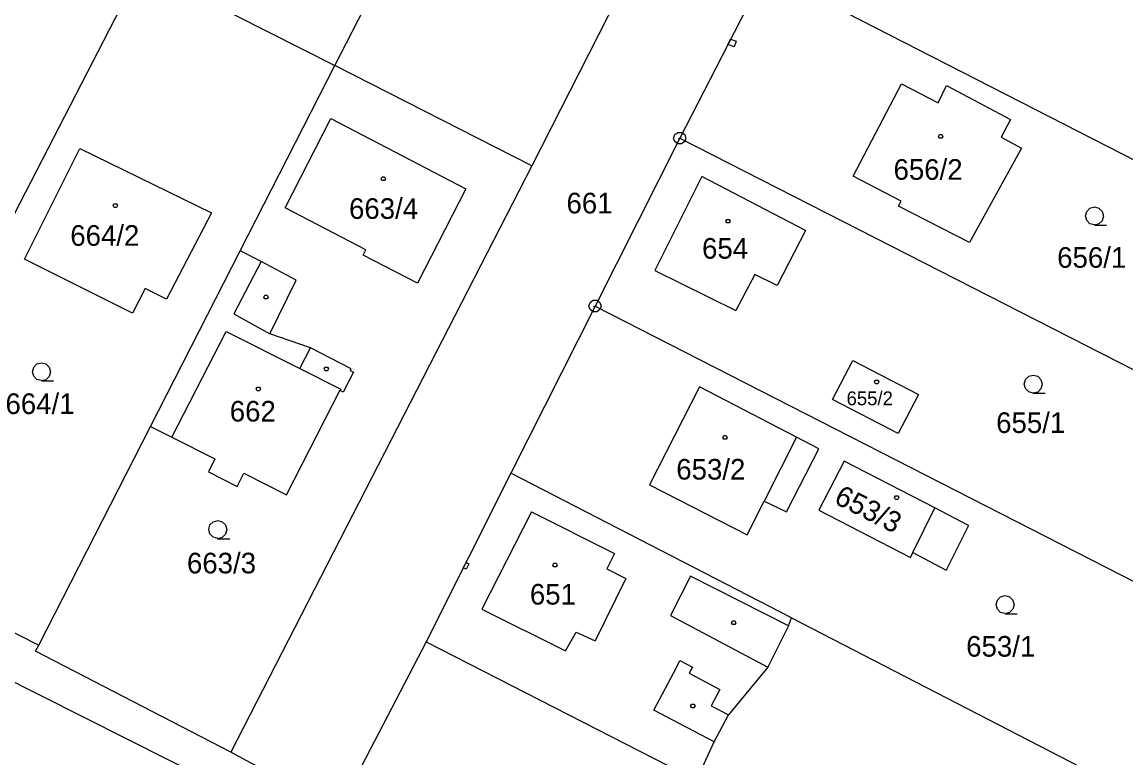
# Model space of a CAD drawing. Extents: x -759699 to -757730, y -1172308 to -1170857.
# Drawn here: x -758455.8 to -758364.9, y -1171339 to -1171278.3 of the extents above; entities that cross this region are included whole.
import ezdxf

# ---------------------------------------------------------------- set-up
doc = ezdxf.new("R2010")
doc.units = 0
for name, color, linetype in [('Vrstva 1', 7, 'Continuous'), ('Vrstva 12', 7, 'Continuous'), ('Vrstva 13', 7, 'Continuous'), ('Vrstva 2', 7, 'Continuous'), ('Vrstva 3', 7, 'Continuous'), ('Vrstva 4', 7, 'Continuous'), ('Vrstva 5', 7, 'Continuous'), ('Vrstva 8', 7, 'Continuous')]:
    doc.layers.add(name, color=color, linetype=linetype)

msp = doc.modelspace()

# ---------------------------------------------------------------- linework, layer by layer
at = {"layer": 'Vrstva 1'}
for p, q in [((-758389.3, -1171241.95), (-758413.82, -1171290.17)), ((-758430.03, -1171281.91), (-758413.88, -1171250.29)), ((-758446, -1171273.82), (-758470.53, -1171321.45)), ((-758446, -1171273.82), (-758430.03, -1171281.91)), ((-758394.57, -1171274.13), (-758401.62, -1171287.89)), ((-758394.57, -1171274.13), (-758332.15, -1171306.13)), ((-758437.83, -1171297.17), (-758430.03, -1171281.91)), ((-758413.82, -1171290.17), (-758430.03, -1171281.91)), ((-758387.33, -1171291.01), (-758383.36, -1171283.42)), ((-758383.36, -1171283.42), (-758380.34, -1171284.98)), ((-758380.34, -1171284.98), (-758379.66, -1171283.54)), ((-758379.66, -1171283.54), (-758374.38, -1171286.36)), ((-758434.14, -1171293.64), (-758430.37, -1171286.28)), ((-758430.37, -1171286.28), (-758419.24, -1171292.06)), ((-758374.38, -1171286.36), (-758375.16, -1171287.82)), ((-758401.62, -1171287.89), (-758408.6, -1171301.73)), ((-758401.62, -1171287.89), (-758339.63, -1171319.54)), ((-758375.16, -1171287.82), (-758373.46, -1171288.72)), ((-758455.6, -1171297.87), (-758451.06, -1171288.75)), ((-758451.06, -1171288.75), (-758440.2, -1171294.05)), ((-758373.46, -1171288.72), (-758377.77, -1171296.48)), ((-758413.82, -1171290.17), (-758438.62, -1171338.48)), ((-758399.8, -1171291.06), (-758403.67, -1171298.79)), ((-758391.26, -1171295.5), (-758399.8, -1171291.06)), ((-758383.39, -1171293.08), (-758387.33, -1171291.01)), ((-758419.24, -1171292.06), (-758423.24, -1171299.85)), ((-758383.61, -1171293.48), (-758383.39, -1171293.08)), ((-758440.2, -1171294.05), (-758443.9, -1171301.16)), ((-758427.48, -1171297.08), (-758434.14, -1171293.64)), ((-758377.77, -1171296.48), (-758383.61, -1171293.48)), ((-758391.26, -1171295.5), (-758393.61, -1171300.02)), ((-758446.7, -1171302.3), (-758455.6, -1171297.87)), ((-758445.23, -1171311.65), (-758437.83, -1171297.17)), ((-758436.12, -1171298.05), (-758437.83, -1171297.17)), ((-758427.71, -1171297.54), (-758427.48, -1171297.08)), ((-758423.24, -1171299.85), (-758427.71, -1171297.54)), ((-758433.23, -1171299.6), (-758436.12, -1171298.05)), ((-758403.67, -1171298.79), (-758397, -1171302.08)), ((-758435.4, -1171304.02), (-758433.23, -1171299.6)), ((-758395.43, -1171299.13), (-758397, -1171302.08)), ((-758393.61, -1171300.02), (-758395.43, -1171299.13)), ((-758445.66, -1171300.27), (-758446.7, -1171302.3)), ((-758443.9, -1171301.16), (-758445.66, -1171300.27)), ((-758408.6, -1171301.73), (-758415.54, -1171315.5)), ((-758408.6, -1171301.73), (-758347.06, -1171333.18)), ((-758432.06, -1171305.17), (-758435.4, -1171304.02)), ((-758428.71, -1171306.9), (-758432.06, -1171305.17)), ((-758428.78, -1171307.03), (-758428.71, -1171306.9)), ((-758389.05, -1171309.42), (-758387.36, -1171306.2)), ((-758387.36, -1171306.2), (-758381.97, -1171309)), ((-758428.51, -1171307.17), (-758429.35, -1171308.81)), ((-758428.78, -1171307.03), (-758428.51, -1171307.17)), ((-758434.02, -1171317.27), (-758429.62, -1171308.68)), ((-758429.35, -1171308.81), (-758429.62, -1171308.68)), ((-758399.99, -1171308.38), (-758404.12, -1171316.44)), ((-758392.01, -1171312.52), (-758399.99, -1171308.38)), ((-758383.63, -1171312.23), (-758389.05, -1171309.42)), ((-758381.97, -1171309), (-758383.63, -1171312.23)), ((-758454.44, -1171329.67), (-758445.23, -1171311.65)), ((-758445.23, -1171311.65), (-758443.47, -1171312.53)), ((-758443.47, -1171312.53), (-758439.92, -1171314.31)), ((-758390.17, -1171313.48), (-758392.01, -1171312.52)), ((-758392.84, -1171318.69), (-758390.17, -1171313.48)), ((-758439.92, -1171314.31), (-758440.46, -1171315.39)), ((-758388.09, -1171314.5), (-758390.17, -1171318.55)), ((-758380.62, -1171318.36), (-758388.09, -1171314.5)), ((-758440.46, -1171315.39), (-758438.09, -1171316.58)), ((-758438.09, -1171316.58), (-758437.55, -1171315.5)), ((-758437.55, -1171315.5), (-758434.02, -1171317.27)), ((-758415.54, -1171315.5), (-758422.51, -1171329.39)), ((-758392.43, -1171327.41), (-758415.54, -1171315.5)), ((-758439.91, -1171341.05), (-758488.47, -1171316.61)), ((-758404.12, -1171316.44), (-758396.08, -1171320.56)), ((-758396.08, -1171320.56), (-758394.68, -1171317.8)), ((-758394.68, -1171317.8), (-758392.84, -1171318.69)), ((-758390.17, -1171318.55), (-758382.62, -1171322.43)), ((-758377.84, -1171319.8), (-758380.62, -1171318.36)), ((-758377.84, -1171319.8), (-758379.69, -1171323.49)), ((-758470.53, -1171321.45), (-758454.44, -1171329.67)), ((-758382.62, -1171322.43), (-758382.42, -1171322.03)), ((-758382.42, -1171322.03), (-758379.69, -1171323.49)), ((-758392.67, -1171328.08), (-758392.43, -1171327.41)), ((-758392.43, -1171327.41), (-758354.46, -1171346.98)), ((-758392.67, -1171328.08), (-758394.36, -1171331.48)), ((-758454.69, -1171330.17), (-758454.44, -1171329.67)), ((-758422.51, -1171329.39), (-758429.75, -1171343.26)), ((-758422.51, -1171329.39), (-758400.25, -1171340.79)), ((-758438.62, -1171338.48), (-758454.69, -1171330.17)), ((-758394.36, -1171331.48), (-758397.61, -1171335.4)), ((-758398.79, -1171337.64), (-758397.61, -1171335.4)), ((-758400.25, -1171340.79), (-758398.79, -1171337.64)), ((-758429.75, -1171343.26), (-758438.62, -1171338.48))]:
    msp.add_line(p, q, dxfattribs=at)
at = {"layer": 'Vrstva 12'}
for p, q in [((-758387.33, -1171291.01), (-758383.36, -1171283.42)), ((-758383.36, -1171283.42), (-758380.34, -1171284.98)), ((-758380.34, -1171284.98), (-758379.66, -1171283.54)), ((-758379.66, -1171283.54), (-758374.38, -1171286.36)), ((-758434.14, -1171293.64), (-758430.37, -1171286.28)), ((-758430.37, -1171286.28), (-758419.24, -1171292.06)), ((-758374.38, -1171286.36), (-758375.16, -1171287.82)), ((-758375.16, -1171287.82), (-758373.46, -1171288.72)), ((-758455.6, -1171297.87), (-758451.06, -1171288.75)), ((-758451.06, -1171288.75), (-758440.2, -1171294.05)), ((-758373.46, -1171288.72), (-758377.77, -1171296.48)), ((-758399.8, -1171291.06), (-758403.67, -1171298.79)), ((-758391.26, -1171295.5), (-758399.8, -1171291.06)), ((-758383.39, -1171293.08), (-758387.33, -1171291.01)), ((-758419.24, -1171292.06), (-758423.24, -1171299.85)), ((-758383.61, -1171293.48), (-758383.39, -1171293.08)), ((-758440.2, -1171294.05), (-758443.9, -1171301.16)), ((-758427.48, -1171297.08), (-758434.14, -1171293.64)), ((-758377.77, -1171296.48), (-758383.61, -1171293.48)), ((-758391.26, -1171295.5), (-758393.61, -1171300.02)), ((-758446.7, -1171302.3), (-758455.6, -1171297.87)), ((-758427.71, -1171297.54), (-758427.48, -1171297.08)), ((-758423.24, -1171299.85), (-758427.71, -1171297.54)), ((-758403.67, -1171298.79), (-758397, -1171302.08)), ((-758395.43, -1171299.13), (-758397, -1171302.08)), ((-758393.61, -1171300.02), (-758395.43, -1171299.13)), ((-758445.66, -1171300.27), (-758446.7, -1171302.3)), ((-758443.9, -1171301.16), (-758445.66, -1171300.27)), ((-758443.47, -1171312.53), (-758439, -1171303.83)), ((-758439, -1171303.83), (-758432.93, -1171306.87)), ((-758432.93, -1171306.87), (-758429.56, -1171308.56)), ((-758389.05, -1171309.42), (-758387.36, -1171306.2)), ((-758387.36, -1171306.2), (-758381.97, -1171309)), ((-758434.02, -1171317.27), (-758429.62, -1171308.68)), ((-758429.56, -1171308.56), (-758429.62, -1171308.68)), ((-758399.99, -1171308.38), (-758404.12, -1171316.44)), ((-758392.01, -1171312.52), (-758399.99, -1171308.38)), ((-758383.63, -1171312.23), (-758389.05, -1171309.42)), ((-758381.97, -1171309), (-758383.63, -1171312.23)), ((-758443.47, -1171312.53), (-758439.92, -1171314.31)), ((-758392.01, -1171312.52), (-758394.68, -1171317.8)), ((-758439.92, -1171314.31), (-758440.46, -1171315.39)), ((-758388.09, -1171314.5), (-758390.17, -1171318.55)), ((-758380.62, -1171318.36), (-758388.09, -1171314.5)), ((-758440.46, -1171315.39), (-758438.09, -1171316.58)), ((-758438.09, -1171316.58), (-758437.55, -1171315.5)), ((-758437.55, -1171315.5), (-758434.02, -1171317.27)), ((-758404.12, -1171316.44), (-758396.08, -1171320.56)), ((-758396.08, -1171320.56), (-758394.68, -1171317.8)), ((-758413.83, -1171318.67), (-758417.94, -1171326.69)), ((-758413.83, -1171318.67), (-758407, -1171322.1)), ((-758390.17, -1171318.55), (-758382.62, -1171322.43)), ((-758382.42, -1171322.03), (-758380.62, -1171318.36)), ((-758407, -1171322.1), (-758407.64, -1171323.37)), ((-758382.62, -1171322.43), (-758382.42, -1171322.03)), ((-758407.64, -1171323.37), (-758406.08, -1171324.16)), ((-758406.08, -1171324.16), (-758408.6, -1171329.31)), ((-758417.94, -1171326.69), (-758411.03, -1171330.14)), ((-758411.03, -1171330.14), (-758410.16, -1171328.58)), ((-758410.16, -1171328.58), (-758408.6, -1171329.31))]:
    msp.add_line(p, q, dxfattribs=at)
at = {"layer": 'Vrstva 13'}
for p, q in [((-758397.67, -1171280.18), (-758397.44, -1171279.73)), ((-758397.44, -1171279.73), (-758396.97, -1171279.89)), ((-758397.14, -1171280.36), (-758397.67, -1171280.18)), ((-758396.97, -1171279.89), (-758397.14, -1171280.36)), ((-758419.46, -1171323.3), (-758419.23, -1171322.86)), ((-758419.21, -1171323.41), (-758419.46, -1171323.3)), ((-758419.23, -1171322.86), (-758419.01, -1171322.95)), ((-758419.01, -1171322.95), (-758419.21, -1171323.41))]:
    msp.add_line(p, q, dxfattribs=at)
at = {"layer": 'Vrstva 3'}
for points in [[(-758367.45, -1171295.04), (-758367.83, -1171294.94), (-758368.1, -1171294.67), (-758368.2, -1171294.3), (-758368.1, -1171293.93), (-758367.83, -1171293.66), (-758367.46, -1171293.56), (-758367.09, -1171293.66), (-758366.82, -1171293.93), (-758366.72, -1171294.31), (-758366.82, -1171294.69), (-758367.09, -1171294.96), (-758367.47, -1171295.06), (-758366.47, -1171295.06)], [(-758454.2, -1171307.87), (-758454.58, -1171307.77), (-758454.85, -1171307.5), (-758454.95, -1171307.13), (-758454.85, -1171306.76), (-758454.58, -1171306.49), (-758454.21, -1171306.39), (-758453.84, -1171306.49), (-758453.57, -1171306.76), (-758453.47, -1171307.14), (-758453.57, -1171307.52), (-758453.84, -1171307.79), (-758454.22, -1171307.89), (-758453.22, -1171307.89)], [(-758372.5, -1171308.89), (-758372.88, -1171308.79), (-758373.15, -1171308.52), (-758373.25, -1171308.15), (-758373.15, -1171307.78), (-758372.88, -1171307.51), (-758372.51, -1171307.41), (-758372.14, -1171307.51), (-758371.87, -1171307.78), (-758371.77, -1171308.16), (-758371.87, -1171308.54), (-758372.14, -1171308.81), (-758372.52, -1171308.91), (-758371.52, -1171308.91)], [(-758439.68, -1171320.87), (-758440.06, -1171320.77), (-758440.33, -1171320.5), (-758440.43, -1171320.13), (-758440.33, -1171319.76), (-758440.06, -1171319.49), (-758439.69, -1171319.39), (-758439.32, -1171319.49), (-758439.05, -1171319.76), (-758438.95, -1171320.14), (-758439.05, -1171320.52), (-758439.32, -1171320.79), (-758439.7, -1171320.89), (-758438.7, -1171320.89)], [(-758374.81, -1171327.06), (-758375.19, -1171326.96), (-758375.46, -1171326.69), (-758375.56, -1171326.32), (-758375.46, -1171325.95), (-758375.19, -1171325.68), (-758374.82, -1171325.58), (-758374.45, -1171325.68), (-758374.18, -1171325.95), (-758374.08, -1171326.33), (-758374.18, -1171326.71), (-758374.45, -1171326.98), (-758374.83, -1171327.08), (-758373.83, -1171327.08)]]:
    msp.add_lwpolyline(points, dxfattribs=at)
at = {"layer": 'Vrstva 4'}
for p, q in [((-758436.12, -1171298.05), (-758438.36, -1171302.37)), ((-758438.36, -1171302.37), (-758435.4, -1171304.02)), ((-758443.47, -1171312.53), (-758439, -1171303.83)), ((-758439, -1171303.83), (-758432.93, -1171306.87)), ((-758432.93, -1171306.87), (-758432.06, -1171305.17)), ((-758432.93, -1171306.87), (-758429.56, -1171308.56)), ((-758429.56, -1171308.56), (-758429.62, -1171308.68)), ((-758392.01, -1171312.52), (-758394.68, -1171317.8)), ((-758413.83, -1171318.67), (-758417.94, -1171326.69)), ((-758413.83, -1171318.67), (-758407, -1171322.1)), ((-758382.42, -1171322.03), (-758380.62, -1171318.36)), ((-758407, -1171322.1), (-758407.64, -1171323.37)), ((-758407.64, -1171323.37), (-758406.08, -1171324.16)), ((-758406.08, -1171324.16), (-758408.6, -1171329.31)), ((-758400.73, -1171323.99), (-758402.39, -1171327.21)), ((-758392.67, -1171328.08), (-758400.73, -1171323.99)), ((-758417.94, -1171326.69), (-758411.03, -1171330.14)), ((-758402.39, -1171327.21), (-758394.36, -1171331.48)), ((-758411.03, -1171330.14), (-758410.16, -1171328.58)), ((-758410.16, -1171328.58), (-758408.6, -1171329.31)), ((-758403.76, -1171335.02), (-758401.87, -1171331.44)), ((-758401.87, -1171331.44), (-758401.61, -1171330.94)), ((-758401.61, -1171330.94), (-758400.58, -1171331.49)), ((-758400.58, -1171331.49), (-758400.85, -1171331.98)), ((-758400.85, -1171331.98), (-758398.32, -1171333.33)), ((-758398.32, -1171333.33), (-758399.03, -1171334.66)), ((-758398.79, -1171337.64), (-758403.76, -1171335.02)), ((-758399.03, -1171334.66), (-758397.61, -1171335.4))]:
    msp.add_line(p, q, dxfattribs=at)
at = {"layer": 'Vrstva 5'}
for points in [[(-758380.04, -1171287.6), (-758379.95, -1171287.75), (-758380.04, -1171287.9), (-758380.22, -1171287.9), (-758380.31, -1171287.75), (-758380.22, -1171287.6)], [(-758425.96, -1171291.09), (-758425.87, -1171291.24), (-758425.96, -1171291.39), (-758426.14, -1171291.39), (-758426.23, -1171291.24), (-758426.14, -1171291.09)], [(-758448.03, -1171293.3), (-758447.94, -1171293.45), (-758448.03, -1171293.6), (-758448.21, -1171293.6), (-758448.3, -1171293.45), (-758448.21, -1171293.3)], [(-758397.56, -1171294.58), (-758397.47, -1171294.73), (-758397.56, -1171294.88), (-758397.74, -1171294.88), (-758397.83, -1171294.73), (-758397.74, -1171294.58)], [(-758435.62, -1171300.83), (-758435.53, -1171300.98), (-758435.62, -1171301.13), (-758435.8, -1171301.13), (-758435.89, -1171300.98), (-758435.8, -1171300.83)], [(-758430.66, -1171306.75), (-758430.57, -1171306.9), (-758430.66, -1171307.05), (-758430.84, -1171307.05), (-758430.93, -1171306.9), (-758430.84, -1171306.75)], [(-758385.31, -1171307.83), (-758385.22, -1171307.98), (-758385.31, -1171308.13), (-758385.49, -1171308.13), (-758385.58, -1171307.98), (-758385.49, -1171307.83)], [(-758436.26, -1171308.4), (-758436.17, -1171308.55), (-758436.26, -1171308.7), (-758436.44, -1171308.7), (-758436.53, -1171308.55), (-758436.44, -1171308.4)], [(-758397.81, -1171312.4), (-758397.72, -1171312.55), (-758397.81, -1171312.7), (-758397.99, -1171312.7), (-758398.08, -1171312.55), (-758397.99, -1171312.4)], [(-758383.66, -1171317.36), (-758383.57, -1171317.51), (-758383.66, -1171317.66), (-758383.84, -1171317.66), (-758383.93, -1171317.51), (-758383.84, -1171317.36)], [(-758411.82, -1171322.91), (-758411.73, -1171323.06), (-758411.82, -1171323.21), (-758412, -1171323.21), (-758412.09, -1171323.06), (-758412, -1171322.91)], [(-758397.09, -1171327.67), (-758397, -1171327.82), (-758397.09, -1171327.97), (-758397.27, -1171327.97), (-758397.36, -1171327.82), (-758397.27, -1171327.67)], [(-758400.46, -1171334.52), (-758400.37, -1171334.67), (-758400.46, -1171334.82), (-758400.64, -1171334.82), (-758400.73, -1171334.67), (-758400.64, -1171334.52)]]:
    msp.add_lwpolyline(points, close=True, dxfattribs=at)
at = {"layer": 'Vrstva 8'}
for p, q in [((-758401.74, -1171287.89), (-758401.5, -1171287.89)), ((-758408.72, -1171301.73), (-758408.48, -1171301.73))]:
    msp.add_line(p, q, dxfattribs=at)
for points in [[(-758401.47, -1171287.41), (-758401.22, -1171287.59), (-758401.12, -1171287.88), (-758401.22, -1171288.17), (-758401.47, -1171288.35), (-758401.78, -1171288.35), (-758402.03, -1171288.17), (-758402.13, -1171287.88), (-758402.03, -1171287.59), (-758401.78, -1171287.41)], [(-758408.45, -1171301.25), (-758408.2, -1171301.43), (-758408.1, -1171301.72), (-758408.2, -1171302.01), (-758408.45, -1171302.19), (-758408.76, -1171302.19), (-758409.01, -1171302.01), (-758409.11, -1171301.72), (-758409.01, -1171301.43), (-758408.76, -1171301.25)]]:
    msp.add_lwpolyline(points, close=True, dxfattribs=at)

# ---------------------------------------------------------------- texts
at = {"layer": 'Vrstva 2'}
for s, height, p in [('656/2', 1.7, (-758384.014, -1171291.32)), ('661', 1.7, (-758410.956, -1171294.09)), ('663/4', 1.7, (-758428.873, -1171294.54)), ('664/2', 1.7, (-758451.837, -1171296.76)), ('654', 1.7, (-758399.791, -1171297.82)), ('656/1', 1.7, (-758370.532, -1171298.57)), ('664/1', 1.7, (-758457.175, -1171310.62)), ('655/2', 1.14, (-758387.884, -1171309.9)), ('662', 1.7, (-758438.698, -1171311.24)), ('655/1', 1.7, (-758375.559, -1171312.18)), ('653/2', 1.7, (-758401.911, -1171316.02)), ('663/3', 1.7, (-758442.223, -1171323.75)), ('651', 1.7, (-758413.973, -1171326.32)), ('653/1', 1.7, (-758378.029, -1171330.61))]:
    msp.add_text(s, height=height, dxfattribs=at).set_placement(p)
msp.add_text('653/3', height=1.7, rotation=333.28955, dxfattribs=at).set_placement((-758389.004, -1171317.928))

doc.saveas('drawing.dxf')
